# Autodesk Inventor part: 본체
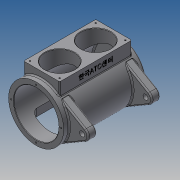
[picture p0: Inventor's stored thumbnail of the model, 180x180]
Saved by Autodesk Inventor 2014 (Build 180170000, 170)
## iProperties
Created: 2016-11
Part Number: 본체
Material: 알루미늄 6061
Document SubType Name: Modeling
Designer: mduedu
Density: 2.71 g/cm^3
Appearance: 기본값
Mass: 2578.2 g
Surface Area: 1746.63 cm^2
Volume: 951.364 cm^3
Author: mduedu
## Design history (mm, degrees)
sketch "스케치1"
  geometry: C1 r 65 at (0, 0); 1 further point
  constraints: 1 centre point, 1 coincident
  dimensions: "d119" = 130 diameter of C1
extrude "돌출1" new body sketch "스케치1" distance "d3" = 98; taper "d4" = 0 deg; dims "d132" = 97, "d133" = 0
feature "쉘1" dims "d120" = 12, "d134" = 8
node "작업 평면2"
sketch "스케치13"
  geometry: L1 (42.5, 85)-(-42.5, 85); L2 (-42.5, 85)-(-42.5, -85); L3 (-42.5, -85)-(42.5, -85); L4 (42.5, -85)-(42.5, 85); 2 further points
  constraints: 8 end point, 2 parallel, 1 horizontal, 1 midpoint, 1 perpendicular, 1 vertical alignment
  dimensions: "d122" = 170 distance of L1.end L2.end; "d124" = 85 distance of L2.end L3.end; "d125" = 85 distance from line of point (0, 0) L1 (= 0.5 x d122)
extrude "돌출11" join sketch "스케치13" stored distance "d126" = 10; taper "d127" = 0 deg
sketch "스케치14"
  geometry: L1 (65, 97)-(-65, 97) reference; C1 r 35 at (0, 42.5); 1 further point
  constraints: 1 centre point, 1 vertical alignment
  dimensions: "d128" = 70 diameter of C1; "d129" = 54.5 distance from line of C1.centre L1
extrude "돌출12" cut sketch "스케치14" stored distance "d130" = 10; taper "d131" = 0 deg
sketch "스케치15"
  geometry: C1 r 53 at (0, 0) reference; 1 further point
extrude "돌출13" cut sketch "스케치15" stored distance "d135" = 10; taper "d136" = 0 deg
chamfer "모따기1" distance "d54" = 1; stored, may be unused: second distance "d55" = 2, angle "d56" = 45 deg
sketch "스케치8"
  geometry: C1 r 23 at (0, 0); C2 r 65 at (0, 0) reference; 1 further point
  constraints: 1 centre point, 1 concentric
  dimensions: "d57" = 46 diameter of C1
extrude "돌출8" join sketch "스케치8" distance "d58" = 14; taper "d59" = 0 deg
feature "면 기울기1" dims angle "d202" = 10 deg
hole "구멍3" diameter "d62" = 24; stored, may be unused: countersink angle "d66" = 90 deg, drill point angle "d68" = 0 deg; dims "d63" = 6, "d64" = 28, "d65" = 8, "d67" = 14, "d169" = 10, "d170" = 10
fillet "모깎기11" dims "d69" = 3
fillet "모깎기12" dims "d70" = 3
fillet "모깎기13" dims "d71" = 0.3
chamfer "모따기2" distance "d72" = 1; stored, may be unused: second distance "d73" = 2, angle "d74" = 45 deg
node "작업 평면3"
sketch "스케치16"
  geometry: L1 (-42.5, -80)-(52.5, -80); L2 (-42.5, -80)-(24.675, -12.825); L3 (-42.5, -80)-(24.675, -147.175); L4 (3.462, -34.038)-(60.057, -67.042); L5 (3.462, -125.962)-(60.057, -92.958); A1 r 65 centre (-42.5, -80) between (3.462, -34.038) and (3.462, -125.962) reference; A2 r 65 centre (-42.5, -80) between (3.462, -125.962) and (3.462, -34.038); A3 r 95 centre (-42.5, -80) between (52.5, -80) and (24.675, -147.175); A4 r 15 centre (52.5, -80) between (60.057, -67.042) and (60.057, -92.958); 1 further point
  constraints: 10 end point, 9 point on circle, 3 centre point, 3 coincident, 2 point on line, 2 tangent, 1 horizontal
  dimensions: "d140" = 45 deg angle of L3 L1; "d141" = 45 deg angle of L2 L1; "d194" = 30 radial gap between concentric circles of A3 A1; "d195" = 30 diameter of A4
extrude "돌출14" join sketch "스케치16" distance "d143" = 20; taper "d144" = 0 deg
fillet "모깎기25" dims "d196" = 3
fillet "모깎기26" dims "d197" = 3
sketch "스케치22"
  geometry: C1 r 6 at (52.5, -80); A1 r 15 centre (52.5, -80) between (60.057, -92.958) and (60.057, -67.042) reference; 1 further point
  constraints: 1 centre point, 1 coincident
  dimensions: "d198" = 12 diameter of C1
extrude "돌출17" cut sketch "스케치22" stored distance "d200" = 10; taper "d201" = 0 deg
fillet "모깎기20" dims "d159" = 3
fillet "모깎기21" dims "d160" = 3
fillet "모깎기22" dims "d161" = 3
node "작업 평면4"
sketch "스케치18"
  geometry: L1 (-42.5, 65)-(42.5, 65); L2 (42.5, 65)-(42.5, -65); L3 (42.5, -65)-(-42.5, -65); L4 (-42.5, -65)-(-42.5, 65); 2 further points
  constraints: 8 end point, 2 parallel, 1 horizontal, 1 midpoint, 1 perpendicular, 1 vertical alignment
  dimensions: "d162" = 130 distance of L1.end L2.end; "d164" = 85 distance of L2.end L3.end; "d165" = 65 distance from line of point (0, 0) L1 (= 0.5 x d162)
extrude "돌출16" cut sketch "스케치18" stored distance "d166" = 15; taper "d167" = 0 deg
fillet "모깎기23" dims "d168" = 10
fillet "모깎기24" dims "d173" = 3
sketch "스케치19"
  geometry: 4 further points
  constraints: 4 other
hole "구멍6" sketch "스케치19" at (0, -59), (59, 0), (-59, 0), (0, 59) diameter "d174" = 3.242; stored, may be unused: countersink angle "d178" = 90 deg, drill point angle "d180" = 120 deg; dims "d175" = 7, "d176" = 4, "d177" = 2, "d179" = 9
sketch "스케치20"
  geometry: L1 (35, -77.5)-(-35, -77.5); L2 (-35, -77.5)-(-35, -7.5); L3 (-35, -7.5)-(35, -7.5); L4 (35, -7.5)-(35, -77.5); L5 (35, -77.5)-(-35, -7.5); L6 (-35, -77.5)-(35, -7.5); C1 r 36 at (0, -42.5) reference; 3 further points
  constraints: 12 end point, 2 coincident, 2 midpoint, 2 parallel, 1 horizontal, 1 perpendicular
  dimensions: "d181" = 70 distance of L2.end L3.end; "d182" = 70 distance of L1.end L2.end
hole "구멍7" sketch "스케치20" at (-35, -77.5), (35, -77.5) diameter "d183" = 3.242; stored, may be unused: countersink angle "d187" = 90 deg, drill point angle "d189" = 118 deg; dims "d184" = 7, "d185" = 4, "d186" = 2, "d188" = 9
sketch "스케치21"
  geometry: L1 (164, 0)-(0, 0) reference; L2 (-3, 0)-(-3, -24.649) reference; 3 further points
  constraints: 1 midpoint, 1 vertical alignment, 1 other
  dimensions: "d190" = 15 distance from line of point (82, -15) L1; "d191" = 85 distance from line of point (82, 0) L2 (derived)
feature "엠보싱2" sketch "스케치21" dims "d119" = 130, "d192" = 0.5, "d193" = 0
node "솔리드1"
mirror "대칭5"
mirror "대칭6"
mirror "대칭7"
